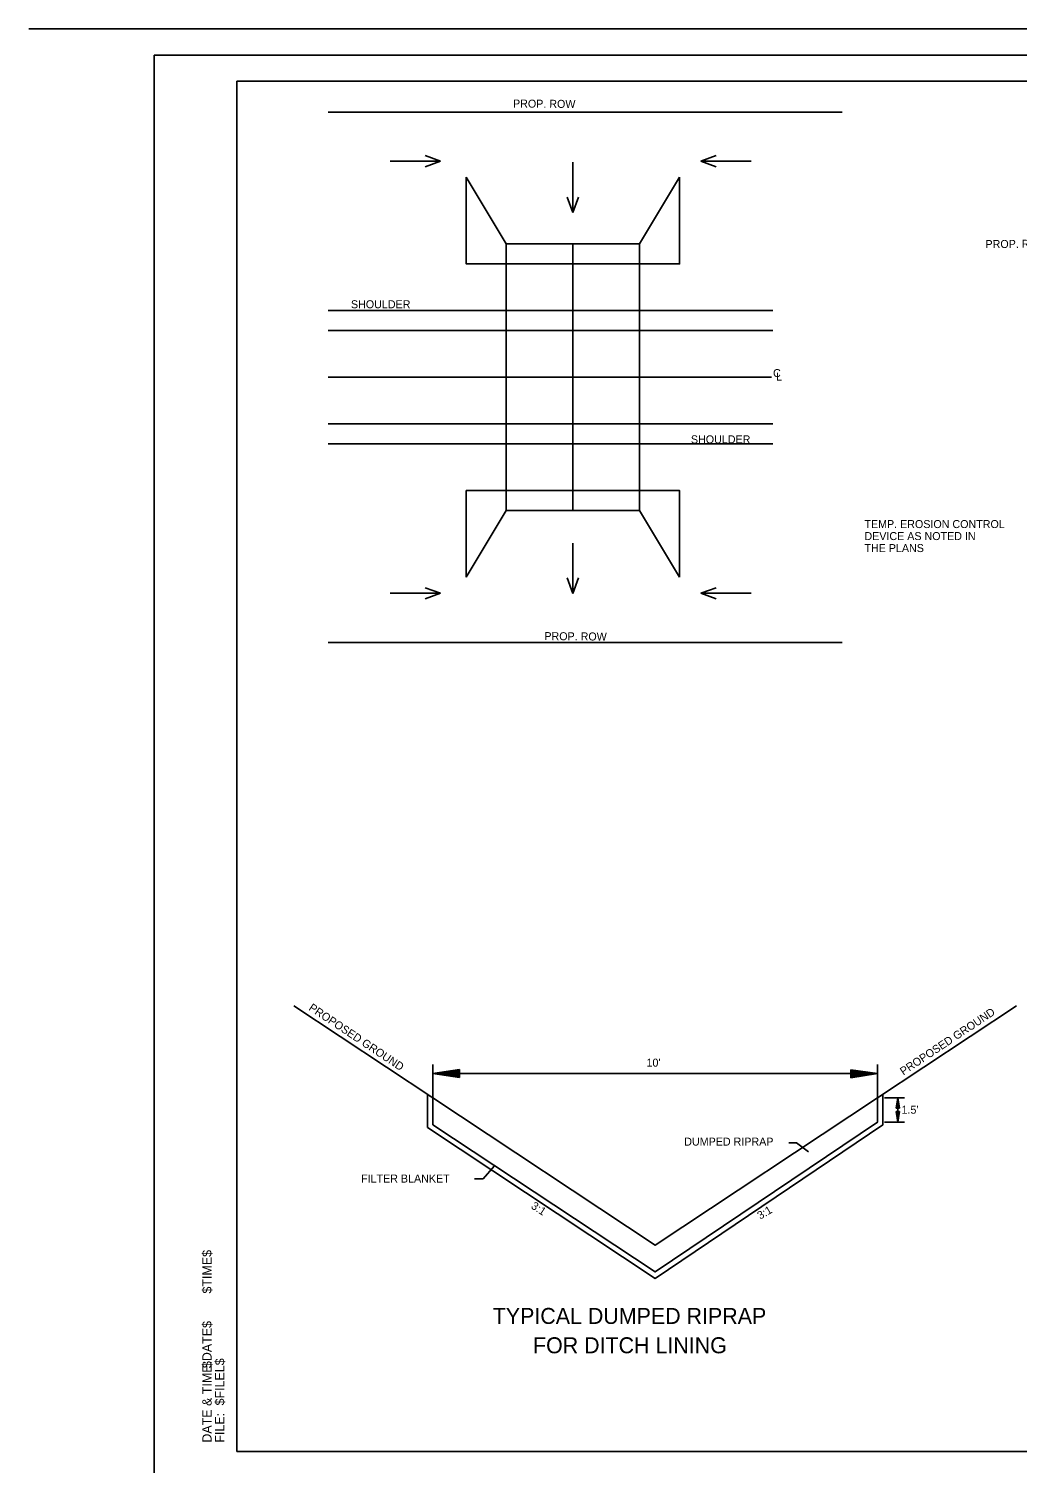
# Model space of a CAD drawing. Extents: x 3575 to 11445, y 9479 to 13278.
# Drawn here: x 5729 to 6470, y 10031 to 11106 of the extents above; entities that cross this region are included whole.
import ezdxf

# ---------------------------------------------------------------- set-up
doc = ezdxf.new("R2010")
doc.units = 0
for name, color, linetype in [('_Drafting 1', 7, 'Continuous'), ('Agg Base Course Text', 7, 'Continuous'), ('CL Construction', 7, 'Continuous'), ('Default', 7, 'Continuous'), ('R_Culvert', 7, 'Continuous'), ('R_Dimension', 7, 'Continuous'), ('R_NoPlot', 7, 'Continuous'), ('R_Proposed Road', 7, 'Continuous'), ('R_Proposed Shoulder', 7, 'Continuous'), ('R_ROW', 7, 'Continuous'), ('R_ROW Annot Labels', 7, 'Continuous'), ('R_Water Annot', 7, 'Continuous'), ('Rock Ditch Liner', 7, 'Continuous'), ('STAMP_PE_CRAFTON-SIGNATURE', 7, 'Continuous'), ('STAMP_PRELIMINARY', 7, 'Continuous'), ('Turn Off', 7, 'Continuous')]:
    doc.layers.add(name, color=color, linetype=linetype)

msp = doc.modelspace()

# ---------------------------------------------------------------- linework, layer by layer
at = {"layer": '_Drafting 1'}
msp.add_lwpolyline([(5884.9, 11066.7), (5884.9, 10039.4), (7465.8, 10039.4), (7465.8, 11002.7), (7250.3, 11002.7), (7250.3, 11001.3), (7234.1, 11001.3), (7234.1, 11017.3), (7054.5, 11017.3), (7054.5, 11066.7)], close=True, dxfattribs=at)
at = {"layer": 'CL Construction'}
msp.add_line((5953.4, 10844.8), (6285.6, 10844.8), dxfattribs=at)
for points in [[(6056.8, 10994.8), (6056.8, 10929.8), (6216.8, 10929.8), (6216.8, 10994.8)], [(6056.8, 10694.8), (6056.8, 10759.8), (6216.8, 10759.8), (6216.8, 10694.8)]]:
    msp.add_lwpolyline(points, dxfattribs=at)
at = {"layer": 'R_Culvert'}
for p, q in [((6086.8, 10944.8), (6056.8, 10994.8)), ((6186.8, 10944.8), (6216.8, 10994.8)), ((6136.8, 10944.8), (6136.8, 10744.8)), ((6086.8, 10744.8), (6056.8, 10694.8)), ((6186.8, 10744.8), (6216.8, 10694.8))]:
    msp.add_line(p, q, dxfattribs=at)
msp.add_lwpolyline([(6086.8, 10944.8), (6186.8, 10944.8), (6186.8, 10744.8), (6086.8, 10744.8)], close=True, dxfattribs=at)
at = {"layer": 'R_Dimension'}
for p, q in [((6379.3, 10296.7), (6380.4, 10304.4)), ((6381.6, 10296.7), (6380.4, 10304.4)), ((6379.3, 10296.7), (6381.6, 10296.7)), ((6379.3, 10294.2), (6380.4, 10286.4)), ((6379.3, 10294.2), (6381.6, 10294.2)), ((6379.5, 10296.7), (6380.4, 10303.1)), ((6379.5, 10294.2), (6380.4, 10287.7)), ((6379.7, 10296.7), (6380.4, 10301.8)), ((6379.7, 10294.2), (6380.4, 10289.1)), ((6379.9, 10296.7), (6380.4, 10300.5)), ((6379.9, 10294.2), (6380.4, 10290.4)), ((6380.1, 10296.7), (6380.4, 10299.2)), ((6380.1, 10294.2), (6380.4, 10291.7)), ((6380.3, 10296.7), (6380.4, 10297.9)), ((6380.3, 10294.2), (6380.4, 10293)), ((6381.4, 10296.7), (6380.4, 10303.1)), ((6381.2, 10296.7), (6380.4, 10301.8)), ((6381, 10296.7), (6380.4, 10300.5)), ((6380.8, 10296.7), (6380.4, 10299.2)), ((6380.6, 10296.7), (6380.4, 10297.9)), ((6381.6, 10294.2), (6380.4, 10286.4)), ((6380.8, 10294.2), (6380.4, 10291.7)), ((6381.2, 10294.2), (6380.4, 10289.1)), ((6381.4, 10294.2), (6380.4, 10287.7)), ((6381, 10294.2), (6380.4, 10290.4)), ((6380.6, 10294.2), (6380.4, 10293))]:
    msp.add_line(p, q, dxfattribs=at)
at = {"layer": 'R_NoPlot'}
msp.add_lwpolyline([(5822.8, 11086.2), (7489.5, 11086.2), (7489.5, 10019.5), (5822.8, 10019.5)], close=True, dxfattribs=at)
at = {"layer": 'R_Proposed Road'}
for p, q in [((5953.4, 10879.8), (6286.8, 10879.8)), ((5953.4, 10809.8), (6286.8, 10809.8))]:
    msp.add_line(p, q, dxfattribs=at)
at = {"layer": 'R_Proposed Shoulder'}
for p, q in [((5953.4, 10894.8), (6286.8, 10894.8)), ((5953.4, 10794.8), (6286.8, 10794.8))]:
    msp.add_line(p, q, dxfattribs=at)
at = {"layer": 'R_ROW'}
for p, q in [((5953.4, 11043.6), (6338.6, 11043.6)), ((5953.4, 10646), (6338.6, 10646))]:
    msp.add_line(p, q, dxfattribs=at)
at = {"layer": 'R_Water Annot'}
for p, q in [((5999.9, 11006.8), (6037.6, 11006.8)), ((6037.6, 11006.8), (6026.1, 11011)), ((6037.6, 11006.8), (6026.1, 11002.6)), ((6136.8, 11006.1), (6136.8, 10968.3)), ((6232.8, 11006.8), (6244.3, 11011)), ((6270.5, 11006.8), (6232.8, 11006.8)), ((6232.8, 11006.8), (6244.3, 11002.6)), ((6136.8, 10968.3), (6132.6, 10979.9)), ((6136.8, 10968.3), (6141, 10979.9)), ((6136.8, 10720.4), (6136.8, 10682.7)), ((6136.8, 10682.7), (6132.6, 10694.3)), ((6136.8, 10682.7), (6141, 10694.3)), ((5999.9, 10682.8), (6037.6, 10682.8)), ((6037.6, 10682.8), (6026.1, 10687)), ((6037.6, 10682.8), (6026.1, 10678.6)), ((6232.8, 10682.8), (6244.3, 10687)), ((6270.5, 10682.8), (6232.8, 10682.8)), ((6232.8, 10682.8), (6244.3, 10678.6))]:
    msp.add_line(p, q, dxfattribs=at)
at = {"layer": 'Rock Ditch Liner'}
for p, q in [((6031.8, 10304.4), (6031.8, 10329.4)), ((6365.2, 10304.4), (6365.2, 10329.4)), ((6031.8, 10322.7), (6365.2, 10322.7)), ((6370.5, 10304.4), (6385.5, 10304.4)), ((6380.4, 10304.4), (6380.4, 10286.4)), ((6370.5, 10286.4), (6385.5, 10286.4))]:
    msp.add_line(p, q, dxfattribs=at)
for points in [[(6369.2, 10304.4), (6369.2, 10284.3), (6198.6, 10169.1), (6027.8, 10282.3), (6027.8, 10304.4)], [(6365.2, 10304.4), (6365.2, 10304.4), (6365.2, 10286.4), (6365.2, 10286.4), (6198.5, 10174), (6031.8, 10284.4), (6031.8, 10284.4), (6031.8, 10304.4)], [(6298.6, 10270.9), (6304.4, 10270.9), (6313.4, 10264)], [(6063, 10243.8), (6069.5, 10243.8), (6077.8, 10253.2)]]:
    msp.add_lwpolyline(points, dxfattribs=at)
at = {"layer": 'STAMP_PE_CRAFTON-SIGNATURE'}
for p, q in [((6051.8, 10325.7), (6031.8, 10322.7)), ((6051.8, 10319.7), (6051.8, 10325.7)), ((6051.8, 10319.7), (6031.8, 10322.7)), ((6051.8, 10325.2), (6035.2, 10322.7)), ((6051.8, 10320.2), (6035.2, 10322.7)), ((6051.8, 10324.7), (6038.6, 10322.7)), ((6051.8, 10320.7), (6038.6, 10322.7)), ((6051.8, 10324.2), (6041.9, 10322.7)), ((6051.8, 10321.2), (6041.9, 10322.7)), ((6051.8, 10323.7), (6045.3, 10322.7)), ((6051.8, 10321.7), (6045.3, 10322.7)), ((6051.8, 10323.2), (6048.7, 10322.7)), ((6051.8, 10322.2), (6048.7, 10322.7)), ((6345.2, 10325.6), (6365.2, 10322.7)), ((6345.2, 10325.6), (6345.3, 10319.6)), ((6345.2, 10325.1), (6361.9, 10322.6)), ((6345.2, 10324.6), (6358.5, 10322.6)), ((6345.2, 10324.1), (6355.1, 10322.6)), ((6345.2, 10323.6), (6351.7, 10322.6)), ((6345.2, 10323.1), (6348.4, 10322.6)), ((6345.2, 10321.6), (6351.7, 10322.6)), ((6345.2, 10320.6), (6358.5, 10322.6)), ((6345.2, 10321.1), (6355.1, 10322.6)), ((6345.2, 10322.1), (6348.4, 10322.6)), ((6345.3, 10319.6), (6365.2, 10322.7)), ((6345.3, 10320.1), (6361.9, 10322.6))]:
    msp.add_line(p, q, dxfattribs=at)
at = {"layer": 'STAMP_PRELIMINARY'}
for p, q in [((7488.8, 11106.1), (5728.8, 11106.1)), ((5884.9, 11066.7), (7465.8, 11066.7)), ((5884.9, 10039.4), (5884.9, 11066.7)), ((7465.8, 10039.4), (5884.9, 10039.4))]:
    msp.add_line(p, q, dxfattribs=at)
at = {"layer": 'Turn Off'}
for p, q in [((5927.6, 10373.5), (6031.8, 10304.4)), ((6469.4, 10373.5), (6365.2, 10304.4))]:
    msp.add_line(p, q, dxfattribs=at)
for points in [[(6365.2, 10286.4), (6365.2, 10304.4), (6369.2, 10307.1), (6369.2, 10284.3), (6369.2, 10284.3), (6198.6, 10169.1), (6027.8, 10282.3), (6027.8, 10282.3), (6027.8, 10307.1), (6031.8, 10304.4), (6031.8, 10284.4)], [(6365.2, 10304.4), (6198.5, 10194), (6031.8, 10304.4)]]:
    msp.add_lwpolyline(points, dxfattribs=at)

# ---------------------------------------------------------------- texts
at = {"layer": 'Agg Base Course Text'}
for s, p in [('TEMP. EROSION CONTROL', (6355.4, 10731.7)), ('DEVICE AS NOTED IN ', (6355.4, 10722.7)), ('THE PLANS', (6355.4, 10713.7))]:
    msp.add_text(s, height=6, dxfattribs=at).set_placement(p)
at = {"layer": 'CL Construction'}
for s, p in [('C', (6286.9, 10844.9)), ('L', (6289.2, 10842.2))]:
    msp.add_text(s, height=6, dxfattribs=at).set_placement(p)
at = {"layer": 'Default'}
for s, height, p in [('$TIME$', 6.98, (5865.9, 10157.8)), ('$DATE$', 6.98, (5865.9, 10101.9)), ('DATE & TIME:', 6.984, (5865.9, 10046)), ('$FILEL$', 6.98, (5875.5, 10073.9)), ('FILE: ', 6.98, (5875.5, 10046))]:
    msp.add_text(s, height=height, rotation=90, dxfattribs=at).set_placement(p)
at = {"layer": 'R_ROW Annot Labels'}
for rotation, p in [(359.565, (6091.9, 11047)), (0.435, (6446.2, 10941.6)), (359.565, (6115.4, 10647.7))]:
    msp.add_text('PROP. ROW', height=6, rotation=rotation, dxfattribs=at).set_placement(p)
at = {"layer": 'STAMP_PE_CRAFTON-SIGNATURE'}
for s, height, p in [('SHOULDER', 6, (5970.4, 10896.5)), ('SHOULDER', 6, (6225.3, 10795.2)), ("10'", 6, (6192, 10327.9)), ("1.5'", 6, (6383.2, 10292.6)), ('DUMPED RIPRAP', 6, (6220.3, 10268.7)), ('FILTER BLANKET', 6, (5978, 10241)), ('TYPICAL DUMPED RIPRAP', 12, (6076.7, 10135)), ('FOR DITCH LINING', 12, (6106.9, 10113))]:
    msp.add_text(s, height=height, dxfattribs=at).set_placement(p)
for s, rotation, p in [('PROPOSED GROUND', 326.2982, (5938.2, 10370.7)), ('PROPOSED GROUND', 33.7018, (6384.6, 10321.2)), ('3:1', 326.6991, (6104.9, 10222.1)), ('3:1', 30.3418, (6277.2, 10213.1))]:
    msp.add_text(s, height=6, rotation=rotation, dxfattribs=at).set_placement(p)

doc.saveas('drawing.dxf')
